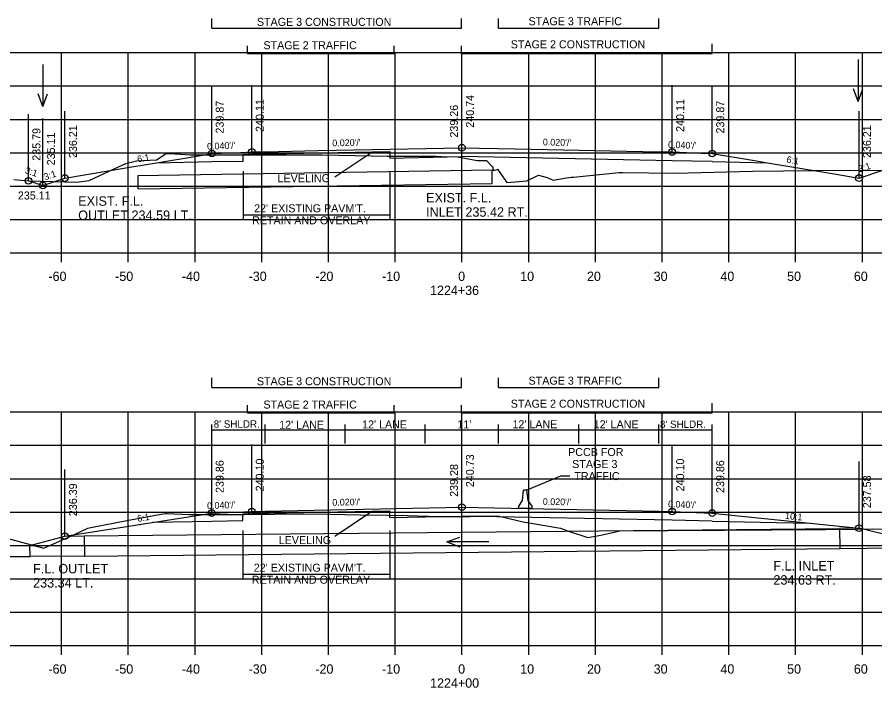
# Model space of a CAD drawing. Extents: x 1342547 to 1344156, y -1532351 to -1517216.
# Drawn here: x 1342636.2 to 1342764.7, y -1531270.8 to -1531170.3 of the extents above; entities that cross this region are included whole.
import ezdxf

# ---------------------------------------------------------------- set-up
doc = ezdxf.new("R2010")
doc.units = 0
for name, color, linetype in [('R_Alt Surface', 7, 'Continuous'), ('R_Axis', 7, 'Continuous'), ('R_Axis Annot', 7, 'Continuous'), ('R_Border Notes', 7, 'Continuous'), ('R_Draft', 7, 'Continuous'), ('R_Exist Surface', 7, 'Continuous'), ('R_Fin Surface', 7, 'Continuous'), ('R_Grid', 7, 'Continuous'), ('R_MOT', 7, 'Continuous'), ('R_No Plot', 7, 'Continuous'), ('R_Water', 7, 'Continuous'), ('R_Xsect Elev', 7, 'Continuous'), ('R_Xsect Slope', 7, 'Continuous')]:
    doc.layers.add(name, color=color, linetype=linetype)

msp = doc.modelspace()

# ---------------------------------------------------------------- linework, layer by layer
at = {"layer": 'R_Alt Surface'}
for points in [[(1342670.07, -1531191.89), (1342670.08, -1531190.92), (1342671.37, -1531190.86), (1342692.07, -1531190.45)], [(1342692.07, -1531190.45), (1342692.08, -1531191.45), (1342702.87, -1531191.23)], [(1342657.09, -1531192.15), (1342665.37, -1531191.98)], [(1342665.37, -1531191.98), (1342670.07, -1531191.89)], [(1342740.37, -1531191.98), (1342734.37, -1531191.86), (1342702.87, -1531191.23)], [(1342740.37, -1531191.98), (1342748.64, -1531192.15)], [(1342670.03, -1531245.72), (1342670.03, -1531244.74), (1342671.37, -1531244.69), (1342692.03, -1531244.28)], [(1342692.03, -1531244.28), (1342692.03, -1531245.28), (1342702.87, -1531245.06)], [(1342656.55, -1531245.99), (1342665.37, -1531245.81)], [(1342665.37, -1531245.81), (1342670.03, -1531245.72)], [(1342740.37, -1531245.81), (1342734.37, -1531245.69), (1342702.87, -1531245.06)], [(1342740.37, -1531245.81), (1342754.87, -1531246.1)]]:
    msp.add_lwpolyline(points, dxfattribs=at)
at = {"layer": 'R_Axis'}
for p, q in [((1342562.87, -1531205.65), (1342842.87, -1531205.65)), ((1342642.87, -1531207.05), (1342642.87, -1531205.65)), ((1342652.87, -1531207.05), (1342652.87, -1531205.65)), ((1342662.87, -1531207.05), (1342662.87, -1531205.65)), ((1342672.87, -1531207.05), (1342672.87, -1531205.65)), ((1342682.87, -1531207.05), (1342682.87, -1531205.65)), ((1342692.87, -1531207.05), (1342692.87, -1531205.65)), ((1342702.87, -1531207.05), (1342702.87, -1531205.65)), ((1342712.87, -1531207.05), (1342712.87, -1531205.65)), ((1342722.87, -1531207.05), (1342722.87, -1531205.65)), ((1342732.87, -1531207.05), (1342732.87, -1531205.65)), ((1342742.87, -1531207.05), (1342742.87, -1531205.65)), ((1342752.87, -1531207.05), (1342752.87, -1531205.65)), ((1342762.87, -1531207.05), (1342762.87, -1531205.65)), ((1342562.87, -1531264.46), (1342842.87, -1531264.46)), ((1342642.87, -1531265.86), (1342642.87, -1531264.46)), ((1342652.87, -1531265.86), (1342652.87, -1531264.46)), ((1342662.87, -1531265.86), (1342662.87, -1531264.46)), ((1342672.87, -1531265.86), (1342672.87, -1531264.46)), ((1342682.87, -1531265.86), (1342682.87, -1531264.46)), ((1342692.87, -1531265.86), (1342692.87, -1531264.46)), ((1342702.87, -1531265.86), (1342702.87, -1531264.46)), ((1342712.87, -1531265.86), (1342712.87, -1531264.46)), ((1342722.87, -1531265.86), (1342722.87, -1531264.46)), ((1342732.87, -1531265.86), (1342732.87, -1531264.46)), ((1342742.87, -1531265.86), (1342742.87, -1531264.46)), ((1342752.87, -1531265.86), (1342752.87, -1531264.46)), ((1342762.87, -1531265.86), (1342762.87, -1531264.46))]:
    msp.add_line(p, q, dxfattribs=at)
at = {"layer": 'R_Draft'}
for p, q in [((1342665.37, -1531171.98), (1342665.37, -1531170.55)), ((1342702.78, -1531171.98), (1342702.78, -1531170.55)), ((1342708.37, -1531171.98), (1342708.37, -1531170.55)), ((1342732.37, -1531171.98), (1342732.37, -1531170.55)), ((1342665.37, -1531171.98), (1342702.78, -1531171.98)), ((1342708.37, -1531171.98), (1342732.37, -1531171.98)), ((1342670.72, -1531175.78), (1342670.72, -1531174.63)), ((1342692.72, -1531175.87), (1342692.72, -1531174.63)), ((1342702.78, -1531175.87), (1342702.78, -1531174.63)), ((1342740.38, -1531175.78), (1342740.38, -1531174.35)), ((1342670.72, -1531175.78), (1342692.72, -1531175.78)), ((1342702.78, -1531175.78), (1342740.38, -1531175.78)), ((1342670.07, -1531193.41), (1342670.07, -1531200.6)), ((1342692.08, -1531193.41), (1342692.08, -1531200.6)), ((1342670.07, -1531199.93), (1342692.08, -1531199.93)), ((1342665.37, -1531225.8), (1342665.37, -1531224.36)), ((1342702.78, -1531225.8), (1342702.78, -1531224.36)), ((1342708.37, -1531225.8), (1342708.37, -1531224.36)), ((1342732.37, -1531225.8), (1342732.37, -1531224.36)), ((1342665.37, -1531225.8), (1342702.78, -1531225.8)), ((1342708.37, -1531225.8), (1342732.37, -1531225.8)), ((1342670.72, -1531229.59), (1342670.72, -1531228.45)), ((1342692.72, -1531229.69), (1342692.72, -1531228.45)), ((1342702.78, -1531229.69), (1342702.78, -1531228.45)), ((1342740.38, -1531229.59), (1342740.38, -1531228.16)), ((1342670.72, -1531229.59), (1342692.72, -1531229.59)), ((1342702.78, -1531229.59), (1342740.38, -1531229.59)), ((1342670.03, -1531247.23), (1342670.03, -1531254.43)), ((1342692.04, -1531247.23), (1342692.04, -1531254.43)), ((1342670.03, -1531253.76), (1342692.04, -1531253.76))]:
    msp.add_line(p, q, dxfattribs=at)
for points in [[(1342717.62, -1531239.08), (1342712.61, -1531241.17)], [(1342719.06, -1531239.08), (1342717.62, -1531239.08)]]:
    msp.add_lwpolyline(points, dxfattribs=at)
at = {"layer": 'R_Exist Surface'}
for points in [[(1342635.73, -1531194.65), (1342637.9, -1531194.85), (1342645.13, -1531195.04), (1342647.01, -1531194.81), (1342650.75, -1531193.06), (1342652.51, -1531192.28), (1342654.08, -1531191.87), (1342657.11, -1531191.71), (1342658.55, -1531190.77), (1342659.91, -1531190.8), (1342662.15, -1531190.97), (1342667.16, -1531190.98), (1342670.3, -1531190.98), (1342679.26, -1531190.95), (1342680.82, -1531190.94), (1342681.93, -1531190.96), (1342691.73, -1531191.15), (1342698.12, -1531191.15), (1342698.98, -1531191.16), (1342699.81, -1531191.19), (1342702.27, -1531191.27), (1342704.6, -1531191.72), (1342705.2, -1531191.82), (1342706.53, -1531191.83), (1342707.37, -1531192.66), (1342707.49, -1531192.78), (1342707.5, -1531192.84), (1342707.57, -1531193.3), (1342708.15, -1531193.15), (1342708.2, -1531193.13), (1342709.61, -1531195.09), (1342712.58, -1531194.84), (1342714.33, -1531194.02), (1342715.63, -1531194.34), (1342716.53, -1531194.76), (1342718.56, -1531194.42), (1342719.25, -1531194.31), (1342719.59, -1531194.29), (1342726.41, -1531193.6), (1342726.91, -1531193.61), (1342734.87, -1531193.73), (1342746.43, -1531193.42), (1342751.05, -1531193.34), (1342755.62, -1531193.33), (1342767.31, -1531193.28)], [(1342622.22, -1531245.03), (1342640.21, -1531249.85), (1342644.81, -1531247.83), (1342646.8, -1531246.88), (1342647.27, -1531246.77), (1342652.67, -1531245.72), (1342657.78, -1531244.77), (1342658.45, -1531244.65), (1342658.62, -1531244.66), (1342662.01, -1531244.81), (1342663.12, -1531244.81), (1342670.23, -1531244.82), (1342674.84, -1531244.78), (1342680.9, -1531244.73), (1342687.62, -1531244.85), (1342691.7, -1531244.93), (1342694.71, -1531244.99), (1342699.42, -1531245.12), (1342700.84, -1531245.14), (1342702.54, -1531245.19), (1342705.56, -1531245.08), (1342708.26, -1531245), (1342712.03, -1531245.9), (1342717.63, -1531246.86), (1342718.98, -1531247.38), (1342721.73, -1531248.28), (1342723.7, -1531247.9), (1342726.54, -1531247.25), (1342729.53, -1531247.2), (1342733.7, -1531247.21), (1342742.26, -1531247.19), (1342749.31, -1531247.11), (1342757.4, -1531247.07), (1342762, -1531247), (1342764.44, -1531246.98), (1342775.4, -1531247.08)]]:
    msp.add_lwpolyline(points, dxfattribs=at)
at = {"layer": 'R_Fin Surface'}
for points in [[(1342638.03, -1531194.85), (1342640.07, -1531195.54), (1342641.1, -1531195.19), (1342643.37, -1531194.44), (1342653.38, -1531192.77), (1342657.09, -1531192.15), (1342663.13, -1531191.14), (1342665.37, -1531190.77), (1342669.74, -1531190.6), (1342671.37, -1531190.53), (1342671.91, -1531190.52), (1342673.37, -1531190.49), (1342681.34, -1531190.33), (1342702.87, -1531189.9), (1342710.84, -1531190.06), (1342732.37, -1531190.49), (1342732.91, -1531190.5), (1342734.37, -1531190.53), (1342738.74, -1531190.71), (1342740.37, -1531190.77), (1342746.4, -1531191.78), (1342748.64, -1531192.15), (1342758.65, -1531193.82), (1342762.37, -1531194.44), (1342765.81, -1531193.29)], [(1342643.37, -1531248.07), (1342665.37, -1531244.6), (1342671.37, -1531244.36), (1342673.37, -1531244.32), (1342702.87, -1531243.73), (1342732.37, -1531244.32), (1342734.37, -1531244.36), (1342740.37, -1531244.6), (1342762.37, -1531246.88)]]:
    msp.add_lwpolyline(points, dxfattribs=at)
at = {"layer": 'R_Grid'}
for p, q in [((1342562.87, -1531175.65), (1342842.87, -1531175.65)), ((1342642.87, -1531205.65), (1342642.87, -1531175.65)), ((1342652.87, -1531205.65), (1342652.87, -1531175.65)), ((1342662.87, -1531205.65), (1342662.87, -1531175.65)), ((1342672.87, -1531205.65), (1342672.87, -1531175.65)), ((1342682.87, -1531205.65), (1342682.87, -1531175.65)), ((1342692.87, -1531205.65), (1342692.87, -1531175.65)), ((1342702.87, -1531205.65), (1342702.87, -1531175.65)), ((1342712.87, -1531205.65), (1342712.87, -1531175.65)), ((1342722.87, -1531205.65), (1342722.87, -1531175.65)), ((1342732.87, -1531205.65), (1342732.87, -1531175.65)), ((1342742.87, -1531205.65), (1342742.87, -1531175.65)), ((1342752.87, -1531205.65), (1342752.87, -1531175.65)), ((1342762.87, -1531205.65), (1342762.87, -1531175.65)), ((1342562.87, -1531180.65), (1342842.87, -1531180.65)), ((1342562.87, -1531185.65), (1342842.87, -1531185.65)), ((1342562.87, -1531190.65), (1342842.87, -1531190.65)), ((1342562.87, -1531195.65), (1342842.87, -1531195.65)), ((1342562.87, -1531200.65), (1342842.87, -1531200.65)), ((1342562.87, -1531205.65), (1342842.87, -1531205.65)), ((1342562.87, -1531229.46), (1342842.87, -1531229.46)), ((1342642.87, -1531264.46), (1342642.87, -1531229.46)), ((1342652.87, -1531264.46), (1342652.87, -1531229.46)), ((1342662.87, -1531264.46), (1342662.87, -1531229.46)), ((1342672.87, -1531264.46), (1342672.87, -1531229.46)), ((1342682.87, -1531264.46), (1342682.87, -1531229.46)), ((1342692.87, -1531264.46), (1342692.87, -1531229.46)), ((1342702.87, -1531264.46), (1342702.87, -1531229.46)), ((1342712.87, -1531264.46), (1342712.87, -1531229.46)), ((1342722.87, -1531264.46), (1342722.87, -1531229.46)), ((1342732.87, -1531264.46), (1342732.87, -1531229.46)), ((1342742.87, -1531264.46), (1342742.87, -1531229.46)), ((1342752.87, -1531264.46), (1342752.87, -1531229.46)), ((1342762.87, -1531264.46), (1342762.87, -1531229.46)), ((1342562.87, -1531234.46), (1342842.87, -1531234.46)), ((1342562.87, -1531239.46), (1342842.87, -1531239.46)), ((1342562.87, -1531244.46), (1342842.87, -1531244.46)), ((1342562.87, -1531249.46), (1342842.87, -1531249.46)), ((1342562.87, -1531254.46), (1342842.87, -1531254.46)), ((1342562.87, -1531259.46), (1342842.87, -1531259.46)), ((1342562.87, -1531264.46), (1342842.87, -1531264.46))]:
    msp.add_line(p, q, dxfattribs=at)
at = {"layer": 'R_MOT'}
for p, q in [((1342711.95, -1531242.75), (1342712.11, -1531241.17)), ((1342712.36, -1531241.17), (1342712.11, -1531241.17)), ((1342712.61, -1531241.17), (1342712.36, -1531241.17)), ((1342712.78, -1531242.75), (1342712.61, -1531241.17)), ((1342711.37, -1531243.58), (1342711.95, -1531242.75)), ((1342713.37, -1531243.58), (1342712.78, -1531242.75)), ((1342711.36, -1531243.92), (1342711.37, -1531243.58)), ((1342713.37, -1531243.92), (1342711.36, -1531243.92)), ((1342713.37, -1531243.92), (1342713.37, -1531243.58))]:
    msp.add_line(p, q, dxfattribs=at)
at = {"layer": 'R_No Plot'}
for centre in [(1342702.87, -1531189.9), (1342702.87, -1531189.9), (1342665.37, -1531190.77), (1342665.37, -1531190.77), (1342671.37, -1531190.53), (1342671.37, -1531190.53), (1342734.37, -1531190.53), (1342734.37, -1531190.53), (1342740.37, -1531190.77), (1342740.37, -1531190.77), (1342637.9, -1531194.85), (1342637.9, -1531194.85), (1342643.37, -1531194.44), (1342643.37, -1531194.44), (1342762.37, -1531194.44), (1342762.37, -1531194.44), (1342640.07, -1531195.54), (1342640.07, -1531195.54), (1342702.87, -1531243.73), (1342702.87, -1531243.73), (1342665.37, -1531244.6), (1342665.37, -1531244.6), (1342671.37, -1531244.36), (1342671.37, -1531244.36), (1342734.37, -1531244.36), (1342734.37, -1531244.36), (1342740.37, -1531244.6), (1342740.37, -1531244.6), (1342762.37, -1531246.88), (1342762.37, -1531246.88), (1342643.37, -1531248.07), (1342643.37, -1531248.07)]:
    msp.add_circle(centre, 0.5, dxfattribs=at)
at = {"layer": 'R_Water'}
for p, q in [((1342640.07, -1531177.44), (1342640.07, -1531183.73)), ((1342762.26, -1531176.71), (1342762.26, -1531183)), ((1342762.26, -1531183), (1342761.56, -1531181.07)), ((1342762.26, -1531183), (1342762.96, -1531181.07)), ((1342640.07, -1531183.73), (1342639.37, -1531181.81)), ((1342640.07, -1531183.73), (1342640.77, -1531181.81)), ((1342654.37, -1531194.05), (1342707.42, -1531193.22)), ((1342707.42, -1531195.23), (1342707.42, -1531193.22)), ((1342654.37, -1531196.06), (1342654.37, -1531194.05)), ((1342654.37, -1531196.06), (1342707.42, -1531195.23)), ((1342646.26, -1531248.04), (1342759.47, -1531246.91)), ((1342700.62, -1531248.94), (1342702.54, -1531248.24)), ((1342706.9, -1531248.94), (1342700.62, -1531248.94)), ((1342700.62, -1531248.94), (1342702.54, -1531249.64)), ((1342646.29, -1531251.04), (1342759.5, -1531249.91)), ((1342634.21, -1531251.12), (1342638.15, -1531251.12))]:
    msp.add_line(p, q, dxfattribs=at)
for points in [[(1342759.47, -1531246.91), (1342759.5, -1531249.91), (1342767.64, -1531249.82), (1342767.63, -1531248.16), (1342762.37, -1531246.88)], [(1342646.26, -1531248.04), (1342646.29, -1531251.04), (1342638.15, -1531251.12), (1342638.13, -1531249.45), (1342643.37, -1531248.07)]]:
    msp.add_lwpolyline(points, close=True, dxfattribs=at)
at = {"layer": 'R_Xsect Elev'}
for p, q in [((1342702.87, -1531189.9), (1342702.87, -1531179.9)), ((1342665.37, -1531190.77), (1342665.37, -1531180.77)), ((1342671.37, -1531190.53), (1342671.37, -1531180.53)), ((1342702.87, -1531191.38), (1342702.87, -1531181.38)), ((1342734.37, -1531190.53), (1342734.37, -1531180.53)), ((1342740.37, -1531190.77), (1342740.37, -1531180.77)), ((1342637.9, -1531194.85), (1342637.9, -1531184.85)), ((1342640.07, -1531195.54), (1342640.07, -1531185.54)), ((1342643.37, -1531194.44), (1342643.37, -1531184.44)), ((1342762.37, -1531194.44), (1342762.37, -1531184.44)), ((1342689.04, -1531190.81), (1342683.84, -1531194.29)), ((1342665.37, -1531244.6), (1342665.37, -1531231.34)), ((1342673.37, -1531234.21), (1342673.37, -1531231.34)), ((1342685.37, -1531234.21), (1342685.37, -1531231.34)), ((1342697.37, -1531234.21), (1342697.37, -1531231.34)), ((1342708.37, -1531234.21), (1342708.37, -1531231.34)), ((1342720.37, -1531234.21), (1342720.37, -1531231.34)), ((1342732.37, -1531234.21), (1342732.37, -1531231.34)), ((1342740.37, -1531244.6), (1342740.37, -1531231.34)), ((1342740.37, -1531232.2), (1342665.37, -1531232.2)), ((1342671.37, -1531244.36), (1342671.37, -1531234.36)), ((1342702.87, -1531243.73), (1342702.87, -1531233.73)), ((1342734.37, -1531244.36), (1342734.37, -1531234.36)), ((1342665.37, -1531244.6), (1342665.37, -1531234.6)), ((1342665.37, -1531244.6), (1342665.37, -1531234.6)), ((1342702.87, -1531245.18), (1342702.87, -1531235.18)), ((1342740.37, -1531244.6), (1342740.37, -1531234.6)), ((1342740.37, -1531244.6), (1342740.37, -1531234.6)), ((1342762.37, -1531246.88), (1342762.37, -1531236.88)), ((1342643.37, -1531248.07), (1342643.37, -1531238.07)), ((1342689, -1531244.63), (1342683.8, -1531248.12))]:
    msp.add_line(p, q, dxfattribs=at)

# ---------------------------------------------------------------- texts
at = {"layer": 'R_Axis Annot'}
for s, p in [('-60', (1342640.9, -1531209.85)), ('-50', (1342650.9, -1531209.85)), ('-40', (1342660.9, -1531209.85)), ('-30', (1342670.9, -1531209.85)), ('-20', (1342680.9, -1531209.85)), ('-10', (1342690.9, -1531209.85)), ('0', (1342702.3, -1531209.85)), ('10', (1342711.6, -1531209.85)), ('20', (1342721.6, -1531209.85)), ('30', (1342731.6, -1531209.85)), ('40', (1342741.6, -1531209.85)), ('50', (1342751.6, -1531209.85)), ('60', (1342761.6, -1531209.85)), ('1224+36', (1342698.09, -1531211.95)), ('-60', (1342640.9, -1531268.66)), ('-50', (1342650.9, -1531268.66)), ('-40', (1342660.9, -1531268.66)), ('-30', (1342670.9, -1531268.66)), ('-20', (1342680.9, -1531268.66)), ('-10', (1342690.9, -1531268.66)), ('0', (1342702.3, -1531268.66)), ('10', (1342711.6, -1531268.66)), ('20', (1342721.6, -1531268.66)), ('30', (1342731.6, -1531268.66)), ('40', (1342741.6, -1531268.66)), ('50', (1342751.6, -1531268.66)), ('60', (1342761.6, -1531268.66)), ('1224+00', (1342698.1, -1531270.76))]:
    msp.add_text(s, height=1.4, dxfattribs=at).set_placement(p)
at = {"layer": 'R_Border Notes'}
for s, height, p in [('EXIST. F.L.', 1.4147, (1342697.5, -1531198.1)), ('EXIST. F.L.', 1.4147, (1342645.36, -1531198.59)), ('OUTLET 234.59 LT.', 1.4147, (1342645.36, -1531200.71)), ('INLET 235.42 RT.', 1.4147, (1342697.5, -1531200.23)), ('F.L. OUTLET', 1.4147, (1342638.6, -1531253.64)), ('F.L. OUTLET', 1.4147, (1342638.6, -1531253.64)), ('F.L. INLET', 1.415, (1342749.54, -1531253.21)), ('F.L. INLET', 1.415, (1342749.54, -1531253.21)), ('233.34 LT.', 1.415, (1342638.6, -1531255.76)), ('233.34 LT.', 1.415, (1342638.6, -1531255.76)), ('234.63 RT.', 1.415, (1342749.54, -1531255.33)), ('234.63 RT.', 1.415, (1342749.54, -1531255.33))]:
    msp.add_text(s, height=height, dxfattribs=at).set_placement(p)
at = {"layer": 'R_Draft'}
for s, p in [('STAGE 3 CONSTRUCTION', (1342672.14, -1531171.65)), ('STAGE 3 TRAFFIC', (1342712.85, -1531171.56)), ('STAGE 2 TRAFFIC', (1342673.12, -1531175.15)), ('STAGE 2 CONSTRUCTION', (1342710.18, -1531175.01)), ("22' EXISTING PAVM'T.", (1342671.72, -1531199.57)), ('RETAIN AND OVERLAY', (1342671.42, -1531201.37)), ('STAGE 3 CONSTRUCTION', (1342672.14, -1531225.47)), ('STAGE 3 TRAFFIC', (1342712.85, -1531225.38)), ('STAGE 2 TRAFFIC', (1342673.12, -1531228.96)), ('STAGE 2 CONSTRUCTION', (1342710.18, -1531228.83)), ('PCCB FOR', (1342718.78, -1531236.07)), ('STAGE 3', (1342719.39, -1531237.87)), ('TRAFFIC', (1342719.72, -1531239.67)), ("22' EXISTING PAVM'T.", (1342671.67, -1531253.39)), ('RETAIN AND OVERLAY', (1342671.38, -1531255.19))]:
    msp.add_text(s, height=1.2, dxfattribs=at).set_placement(p)
at = {"layer": 'R_Xsect Elev'}
for s, p in [('239.87', (1342667.17, -1531187.77)), ('240.11', (1342673.17, -1531187.53)), ('240.74', (1342704.67, -1531186.9)), ('240.11', (1342736.17, -1531187.53)), ('239.87', (1342742.17, -1531187.77)), ('239.26', (1342702.27, -1531188.38)), ('236.21', (1342645.17, -1531191.44)), ('236.21', (1342764.17, -1531191.44)), ('235.79', (1342639.7, -1531191.85)), ('235.11', (1342641.87, -1531192.54)), ('239.86', (1342667.17, -1531241.6)), ('240.10', (1342673.17, -1531241.36)), ('240.73', (1342704.67, -1531240.73)), ('240.10', (1342736.17, -1531241.36)), ('239.86', (1342742.17, -1531241.6)), ('239.28', (1342702.27, -1531242.18)), ('237.58', (1342764.17, -1531243.88)), ('236.39', (1342645.17, -1531245.07))]:
    msp.add_text(s, height=1.2, rotation=90, dxfattribs=at).set_placement(p)
for s, height, p in [('LEVELING', 1.2, (1342675.24, -1531195.06)), ('235.11', 1.2, (1342636.32, -1531197.65)), ("8' SHLDR.", 1.1, (1342665.67, -1531231.82)), ("12' LANE", 1.2, (1342675.48, -1531231.99)), ("12' LANE", 1.2, (1342687.91, -1531231.94)), ("11'", 1.2, (1342702.18, -1531231.94)), ("12' LANE", 1.2, (1342710.44, -1531231.91)), ("12' LANE", 1.2, (1342722.61, -1531231.92)), ("8' SHLDR.", 1.1, (1342732.54, -1531231.86)), ('LEVELING', 1.2, (1342675.41, -1531249.25))]:
    msp.add_text(s, height=height, dxfattribs=at).set_placement(p)
at = {"layer": 'R_Xsect Slope'}
for s, rotation, p in [("0.040'/'", 2.2906, (1342664.69, -1531190.2)), ("0.020'/'", 1.1458, (1342683.45, -1531189.69)), ("0.020'/'", 358.8542, (1342714.98, -1531189.54)), ("0.040'/'", 357.7094, (1342733.74, -1531189.91)), ('6:1', 9.4623, (1342654.28, -1531192.11)), ('6:1', 350.5377, (1342751.45, -1531192.11)), ('3:1', 341.5651, (1342637.3, -1531193.68)), ('3:1', 18.4349, (1342762.45, -1531193.61)), ('3:1', 18.4349, (1342640.4, -1531194.79)), ("0.040'/'", 2.2906, (1342664.69, -1531244.02)), ("0.020'/'", 1.1458, (1342683.45, -1531243.51)), ("0.020'/'", 358.8542, (1342714.98, -1531243.37)), ("0.040'/'", 357.7094, (1342733.74, -1531243.73)), ('10:1', 354.2095, (1342751.25, -1531245.47)), ('6:1', 9.4623, (1342654.28, -1531245.94))]:
    msp.add_text(s, height=1, rotation=rotation, dxfattribs=at).set_placement(p)

doc.saveas('drawing.dxf')
